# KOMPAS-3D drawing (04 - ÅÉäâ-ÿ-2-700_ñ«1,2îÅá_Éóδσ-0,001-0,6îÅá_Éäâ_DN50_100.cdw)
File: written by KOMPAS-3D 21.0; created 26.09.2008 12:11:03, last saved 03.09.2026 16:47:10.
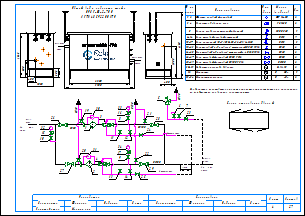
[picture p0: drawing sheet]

Sheets 1-2: A3, landscape

Document properties: Наименование: Макро:21; Автор: RaskoAdmin; Форматы листов документа: 2xA3; Полное имя файла: \\UR38nt01\Departments\КТО\КБ ПУРДГ\Заявки\Прайс-лист на типовые шкафы ГРПШ\ПРДГ_стандарт_20_03_2026\ПРДГ с РДГ(Н, В)\ПРДГ-Ш-2-700_до1,2МПа_Рвых-0,001-0,6МПа_РДГ_DN50_100.cdw

Title block, sheet 1: Наименование: Пункт учета газа / ПУГ-Ш-400-Р / ЛГТИ.485922.001ТУ; designation: ЛГТИ.03.4411141; sheet number: 1; Количество листов документа: 2; organisation: ООО "ЭЛЬСТЕР Газэлектроника"; Форматы листов документа: A3; stored path: C:\Рабочие документы\Компас\ПУГ\Схема.cdw; Разработал: Устинов; Проверил: Кошкин; Утвердил: Кошкин
Title block, sheet 2: sheet number: 2; stored path: D:\Рабочие документы\Заявки\ПУРДГ\ПУРДГ-ШУЭО-2-100-Р 4411220.cdw; designation, second copy: ЛГТИ.03.4411141-

Views: Вид 1, Вид 2
Referenced files: wcvoit.frw
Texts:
  Normal
  № на
  схеме
  Усл.
  обозн.
  Марка
  (модель)
  Кол.
  Фильтр газовый фланцевый
  ФГ 16-50
  Регулятор давления газа
  РДГ-50
  Клапан предохранительный сбросной
  КПС DN20
  Кран шаровой газовый латунный
  DN15
  Кран кнопочный VE-РАСКО-НЗ-1,6-G1/2-М20
  Кран шаровой "под приварку" штуцерный DN20 PN16
  Кран шаровой "под приварку" штуцерный п/п DN20 PN16
  DN20
  Кран шаровой фланцевый DN50 PN16
  Кран шаровой фланцевый DN100 PN16
  DN50
  DN100
  Индикатор перепада давления
  Delta 15
  Манометр
  Манометр-напоромер
  0...     МПа
  0...     кПа
  Общий вид и габариты шкафа
  ПРДГ-Ш-2-700
  Выход газа
  Вход газа
  logo-rasko-ge.png
  Вход
  газа
  PDI
  Выход
  Р=     кПа
  Импульс DN20
  ≥5DN
  HYSWLongFangSong
  Р=       МПа
  Схема открывания дверей
  Предприятие изготовитель может заменять комплектующие на аналогичные,
  не ухудшающие заявленных характеристик.
  Должность
  Конструктор
  Фамилия
  Подпись
  Дата
  Согласовано
  Максимкин
  Лист
  Листов
  POLYLINE_STYLE_0.18_RGB_0_0_0
  POLYLINE_STYLE_0.50_RGB_0_0_0
  POLYLINE_STYLE_0.34_RGB_0_0_0
  PHANTOM_RGB_0_0_0_SC_1_THICK_0.18
  K5LT_THIN_RGB_0_0_0_THICK_0.18
  K5LT32769_RGB_0_0_0_THICK_0.18
  K5LT12_RGB_0_0_0_SC_1_THICK_0.18
  K5LT_DASHED_RGB_0_0_0_SC_1_THICK_0.18
  ACISOTGL_RGB_0_0_0_SC_0.8_THICK_0.25
  CONTINUOUS_RGB_0_127_31_THICK_0.3
  CONTINUOUS_RGB_0_0_255_THICK_0.35
  CONTINUOUS_RGB_255_0_0_THICK_0.35
  POLYLINE_STYLE_0.25_RGB_0_0_0
  CONTINUOUS_RGB_0_0_0_THICK_0.5
  POLYLINE_STYLE_0.35_RGB_0_0_255
  CONTINUOUS_RGB_0_0_0_THICK_0.4
  CONTINUOUS_RGB_0_0_0_THICK_0.35
  Без оформления
Dimensions and other numbers on the sheet: 1; 1, 2; 2; 3, 4; 5; 6-14; 9; 15-17; 3; 18-23; 24-25; 6; 26-27; 28-29; 30-31; 32; 33-34; 400; 1050; 500; 305; 1565; 3100; 1000; 4130; 2800; 4; 10; 27; 28; 29; 23; 8; 12; 19; 20; 21; 22; 25; 24; 30; 31; 15; 16; 26; 7; 11; 14; 13; 33; 17; 34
